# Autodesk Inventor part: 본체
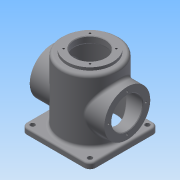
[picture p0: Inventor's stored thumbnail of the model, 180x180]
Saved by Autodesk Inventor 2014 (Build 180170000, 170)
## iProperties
Created: 2015-10
Part Number: 본체
Material: Generic
Document SubType Name: Modeling
Designer: SDA
Density: 1 g/cm^3
Appearance: Default
Author: SDA
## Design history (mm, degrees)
sketch "스케치1"
  geometry: L1 (-60, -60)-(60, -60); L2 (60, -60)-(60, 60); L3 (60, 60)-(-60, 60); L4 (-60, 60)-(-60, -60); L5 (-60, -60)-(60, 60); L6 (60, -60)-(-60, 60); 1 further point
  constraints: 12 end point, 2 midpoint, 2 parallel, 1 horizontal, 1 perpendicular
  dimensions: "d0" = 120 distance of L2.end L3.end; "d1" = 120 distance of L1.end L2.end
extrude "돌출1" new body sketch "스케치1" distance "d2" = 10; taper "d3" = 0 deg
sketch "스케치2"
  geometry: C1 r 50 at (0, 0); 1 further point
  constraints: 1 centre point, 1 coincident
  dimensions: "d4" = 100 diameter of C1
extrude "돌출2" join sketch "스케치2" distance "d5" = 110; taper "d6" = 0 deg
sketch "스케치3"
  geometry: C1 r 50 at (0, 0) reference; C2 r 40 at (0, 0)
  constraints: 1 centre point, 1 coincident
  dimensions: "d7" = 80 diameter of C2
extrude "돌출3" join sketch "스케치3" distance "d8" = 5; taper "d9" = 0 deg
sketch "스케치4"
  geometry: L1 (60, -60)-(-60, -60) reference; L2 (60, 60)-(60, -60) reference; L3 (-60, 60)-(60, 60) reference; L4 (-60, -60)-(-60, 60) reference; 1 further point
sketch "스케치5"
  geometry: L1 (-60, 0)-(-60, 10) reference; L2 (-60, 10)-(-50, 10) reference; L3 (-50, 10)-(-50, 120) reference; L4 (-50, 120)-(-40, 120) reference; L5 (-40, 120)-(-40, 125) reference; L6 (-40, 125)-(40, 125) reference; L7 (40, 125)-(40, 120) reference; L8 (40, 120)-(50, 120) reference; L9 (50, 120)-(50, 10) reference; L10 (50, 10)-(60, 10) reference; L11 (60, 10)-(60, 0) reference; L12 (60, 0)-(-60, 0) reference; L13 (65, 60)-(-65, 60); L14 (65, 100)-(0, 100); L15 (65, 100)-(65, 60); L16 (-65, 60)-(-65, 100); L17 (-65, 100)-(0, 100); 1 further point
  constraints: 10 end point, 1 collinear, 1 parallel, 1 perpendicular
  dimensions: "d12" = 60 distance between parallel lines of L12 L13; "d13" = 40 distance between parallel lines of L13 L14; "d15" = 40 distance of L13.end L16.end; "d16" = 65 distance of L16.end L14.end
revolve "회전1" sketch "스케치5" stored, may be unused: angle "d17" = 90 deg
sketch "스케치6"
  geometry: C1 r 40 at (0, 0) reference; C2 r 27 at (0, 0); 1 further point
  constraints: 1 centre point, 1 coincident
  dimensions: "d18" = 54 diameter of C2
extrude "돌출4" cut sketch "스케치6" stored distance "d19" = 10; taper "d20" = 0 deg
sketch "스케치7"
  geometry: C1 r 45 at (0, 0); 1 further point
  constraints: 1 centre point, 1 coincident
  dimensions: "d21" = 90 diameter of C1
extrude "돌출5" cut sketch "스케치7" distance "d22" = 112; taper "d23" = 0 deg
sketch "스케치8"
  geometry: C1 r 40 at (0, 0) reference; C2 r 27 at (0, 0)
  constraints: 1 centre point, 1 coincident
  dimensions: "d24" = 54 diameter of C2
extrude "돌출6" cut sketch "스케치8" distance "d25" = 13; taper "d26" = 0 deg
sketch "스케치9"
  geometry: L1 (60, 60)-(-60, 60) reference; L2 (-60, 60)-(-60, -60) reference; 4 further points
  constraints: 2 horizontal alignment, 2 vertical alignment
  dimensions: "d27" = 100 distance of point (50, -50) point (50, 50); "d28" = 10 distance from line of L1 point (50, 50); "d29" = 100 distance of point (-50, 50) point (50, 50); "d30" = 10 distance from line of L2 point (-50, 50)
hole "구멍1" sketch "스케치9" at (-50, 50), (50, 50), (50, -50), (-50, -50) diameter "d31" = 8; stored, may be unused: countersink angle "d35" = 90 deg, drill point angle "d37" = 118 deg; dims "d32" = 6, "d33" = 4, "d34" = 2, "d36" = 8
sketch "스케치10" dims "d39" = 65
  geometry: L1 (0, 0)-(37.055, 0); L2 (0, 0)-(22.981, 22.981); C1 r 40 at (0, 0) reference; 2 further points
  constraints: 4 end point, 2 coincident, 1 horizontal, 3 other
  dimensions: "d38" = 45 deg angle of L1 L2
hole "구멍2" sketch "스케치10" at (22.981, 22.981) diameter "d40" = 3.242; stored, may be unused: countersink angle "d44" = 82 deg, drill point angle "d46" = 118 deg; dims "d41" = 6, "d42" = 3.023, "d43" = 2, "d45" = 8
sketch "스케치11" dims "d50" = 65
  geometry: L1 (0, 0)-(-32.5, 0); C1 r 40 at (0, 0) reference; 2 further points
  constraints: 2 coincident, 2 end point, 1 horizontal, 1 horizontal alignment, 2 other
hole "구멍3" sketch "스케치11" at (-32.5, 0) diameter "d51" = 3.242; stored, may be unused: countersink angle "d55" = 82 deg, drill point angle "d57" = 118 deg; dims "d52" = 6, "d53" = 3.023, "d54" = 2, "d56" = 8
node "작업 평면1"
sketch "스케치12"
  geometry: L1 (-60, 0)-(60, 0) reference; L2 (60, 0)-(60, 10) reference; 2 further points
  constraints: 1 other
  dimensions: "d62" = 70 distance from line of L1 point (0, 70)
feature "엠보싱1" sketch "스케치12" dims "d0" = 120, "d1" = 120, "d64" = 0.5, "d65" = 0
fillet "모깎기1" dims "d66" = 5
fillet "모깎기2" dims "d67" = 10
fillet "모깎기3" dims "d68" = 3
chamfer "모따기1" distance "d69" = 3; stored, may be unused: second distance "d70" = 2, angle "d71" = 45 deg
chamfer "모따기2" distance "d72" = 1; stored, may be unused: second distance "d73" = 2, angle "d74" = 45 deg
node "솔리드1"
pattern_circular "원형 패턴1" dims angle "d48" = 360 deg
pattern_circular "원형 패턴2" dims angle "d59" = 360 deg
mirror "대칭1"
node "절단 모서리 투영1"
